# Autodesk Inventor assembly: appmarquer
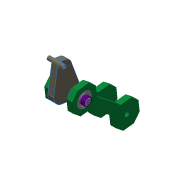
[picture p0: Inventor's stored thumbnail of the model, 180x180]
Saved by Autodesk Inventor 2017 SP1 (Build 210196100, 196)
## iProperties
Created: 2006-05
Part Number: appmarquer
Document SubType Name: Assembly
Designer: Administrateur
Manufacturer: Standard
Standards Organization: Custom
Author: Administrateur
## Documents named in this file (7)
- H:\Consmec\TSsi\02-Cours\02-03-RDM\02-03-02-Cisaillement\02-03-02-02-Exercices Cisaillement\02-03-02-02-02-Exercice Cisaillement 2\02-03-02-02-02-02-Dessin ExCisaillement2\appmarquer.iam
- H:\Consmec\TSsi\02-Cours\02-03-RDM\02-03-02-Cisaillement\02-03-02-02-Exercices Cisaillement\02-03-02-02-02-Exercice Cisaillement 2\02-03-02-02-02-02-Dessin ExCisaillement2\Roulement 6203 J30.iam
- H:\Consmec\TSsi\02-Cours\02-03-RDM\02-03-02-Cisaillement\02-03-02-02-Exercices Cisaillement\02-03-02-02-02-Exercice Cisaillement 2\02-03-02-02-02-02-Dessin ExCisaillement2\arbreex2.ipt
- H:\Consmec\TSsi\02-Cours\02-03-RDM\02-03-02-Cisaillement\02-03-02-02-Exercices Cisaillement\02-03-02-02-02-Exercice Cisaillement 2\02-03-02-02-02-02-Dessin ExCisaillement2\bielletteex2.ipt
- H:\Consmec\TSsi\02-Cours\02-03-RDM\02-03-02-Cisaillement\02-03-02-02-Exercices Cisaillement\02-03-02-02-02-Exercice Cisaillement 2\02-03-02-02-02-02-Dessin ExCisaillement2\bagueex2.ipt
- H:\Consmec\TSsi\02-Cours\02-03-RDM\02-03-02-Cisaillement\02-03-02-02-Exercices Cisaillement\02-03-02-02-02-Exercice Cisaillement 2\02-03-02-02-02-02-Dessin ExCisaillement2\goupilleex2.ipt
- H:\Consmec\TSsi\02-Cours\02-03-RDM\02-03-02-Cisaillement\02-03-02-02-Exercices Cisaillement\02-03-02-02-02-Exercice Cisaillement 2\02-03-02-02-02-02-Dessin ExCisaillement2\levierex2.ipt
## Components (10 placed, 6 different names)
1. Roulement 6203 J30:1 [sub-assembly] — Logement:1, Logement:3, Logement:7
2. Roulement 6203 J30:2 [sub-assembly] — Logement:2, Logement:4, Logement:6
3. arbreex2:1 — Logement:1, Logement:2, Affleurer:1, Affleurer:2, Affleurer:3, Affleurer:4, Plaquer:1, Plaquer:2, Affleurer:6, Orientation:3
4. bielletteex2:1 — Logement:3, Orientation:1, Orientation:2, Logement:8
5. bielletteex2:2 — Logement:4, Orientation:2
6. bagueex2:1 — Logement:7, Affleurer:1, Orientation:1
7. bagueex2:2 — Logement:6, Affleurer:2, Affleurer:5
8. goupilleex2:1 — Affleurer:3, Affleurer:4, Plaquer:1
9. goupilleex2:2 — Affleurer:5, Plaquer:2, Affleurer:6
10. levierex2:1 — Orientation:3, Logement:8
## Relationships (18: Insert 7, Flush 6, Angle 3, Mate 2)
- Logement:1 [Insert]: Roulement 6203 J30:1 ↔ arbreex2:1
- Logement:2 [Insert]: Roulement 6203 J30:2 ↔ arbreex2:1
- Logement:3 [Insert]: Roulement 6203 J30:1 ↔ bielletteex2:1
- Logement:4 [Insert]: Roulement 6203 J30:2 ↔ bielletteex2:2
- Logement:6 [Insert]: Roulement 6203 J30:2 ↔ bagueex2:2
- Logement:7 [Insert]: Roulement 6203 J30:1 ↔ bagueex2:1
- Affleurer:1 [Flush]: arbreex2:1 ↔ bagueex2:1
- Affleurer:2 [Flush]: arbreex2:1 ↔ bagueex2:2
- Affleurer:3 [Flush]: arbreex2:1 ↔ goupilleex2:1
- Affleurer:4 [Flush]: arbreex2:1 ↔ goupilleex2:1
- Plaquer:1 [Mate]: arbreex2:1 ↔ goupilleex2:1
- Affleurer:5 [Flush]: bagueex2:2 ↔ goupilleex2:2
- Plaquer:2 [Mate]: arbreex2:1 ↔ goupilleex2:2
- Affleurer:6 [Flush]: arbreex2:1 ↔ goupilleex2:2
- Orientation:1 [Angle]: bielletteex2:1 ↔ bagueex2:1
- Orientation:2 [Angle]: bielletteex2:1 ↔ bielletteex2:2
- Orientation:3 [Angle]: arbreex2:1 ↔ levierex2:1
- Logement:8 [Insert]: bielletteex2:1 ↔ levierex2:1
